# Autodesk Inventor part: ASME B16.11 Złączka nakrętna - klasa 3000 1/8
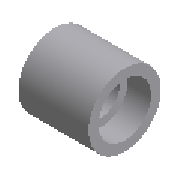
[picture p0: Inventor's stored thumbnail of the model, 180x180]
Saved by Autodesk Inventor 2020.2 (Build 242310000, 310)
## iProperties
Manager: www.cadconsulting.pl
Company: Fabian Stasiak CAD Consulting
Created: 2014-02
Part Number: ASME B16.11 Złączka nakrętna - klasa 3000 1/8
Material: Stal
Description: Złączka nakrętna, kuta, do przyspawania - klasa 3000
Document SubType Name: Modeling
Standard: ASME B16.11
Designer: F.Stasiak
Standard Revision: 2005
Standards Organization: ANSI
Language: pl-PL
Size Designation: 1/8
Categories: <MemberInstance><Categories><Category DisplayName="Rury cienko- i grubościenne" InternalName="4347fa0f-2144-441d-94cd-e3e15c92b736" Mnemonic="TUBEANDPIPE"><Cate
Density: 1 g/cm^3
Appearance: Płyta
Catalog Web Link: www.expertbooks.pl
NAME: PIPING: ASME B16.11 Coupling - Class 3000
DATA: <meta><inlinegroups number="1" deflen="2.8956"></inlinegroups><connections number="2"></connections><angles><a>3.14159265358979</a></angles></meta>
IsCustomPart: 0
Author: F.Stasiak
Subject: Zbiór ćwiczeń. Autodesk Inventor 2020. Kurs Professional
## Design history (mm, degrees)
sketch "Sketch1"
  geometry: L1 (0, 0)-(25.654, 0); L2 (0, 0)-(0, 5.334); L3 (0, 5.334)-(9.652, 5.334); L4 (9.652, 5.334)-(9.652, 3.035); L5 (9.652, 3.035)-(16.002, 3.035); L6 (16.002, 3.035)-(16.002, 5.334); L7 (16.002, 5.334)-(25.654, 5.334); L8 (25.654, 5.334)-(25.654, 8.509); L9 (25.654, 8.509)-(0, 8.509); L10 (0, 8.509)-(0, 5.334); L11 (25.654, 5.334)-(25.654, 0)
  constraints: 22 end point, 6 perpendicular, 3 parallel, 1 collinear, 1 horizontal, 1 point on line
  dimensions: "d0" = 6.0706 diameter of L5 L1 (= D); "d1" = 10.668 diameter of L3 L1 (= B); "d2" = 3.175 distance between parallel lines of L3 L9 (= C1); "d3" = 9.652 distance between parallel lines of L10 L4 (= J1); "d4" = 6.35 distance between parallel lines of L4 L6 (= E1); "d5" = 9.652 distance between parallel lines of L6 L8 (= J1)
revolve "Revolve1" sketch "Sketch1" stored, may be unused: angle "d6" = 90 deg
workaxis "Work Axis1"
workpoint "Work Point1"
workpoint "Work Point2"
workaxis "Work Axis2"
workpoint "Work Point3"
workpoint "Work Point4"
body "Solid1"
other parameters: "B" = 10.668 [user parameter; used in 1 equation term], "D" = 6.0706 [user parameter; used in 1 equation term], "C1" = 3.175 [user parameter; used in 1 equation term], "J1" = 9.652 [user parameter; used in 2 equation terms], "E1" = 6.35 [user parameter; used in 1 equation term], "Size_Designation" = 1.25 [user parameter]
